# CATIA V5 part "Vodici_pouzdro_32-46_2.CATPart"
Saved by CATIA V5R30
Part number: Vodici_pouzdro_32-46_2
Definition: E 1100_32-46
Nomenclature: E 1100_32-46
Source: Unknown
Description: PART--DESC
Bounding box of the stored display mesh (mm): x 163.7 to 210.3, y 113.7 to 160.3, z -101 to -46
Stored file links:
  E:\Bakalarka\Model\Forma_v7\Vodici_pouzdro_32-46_2.CATPart
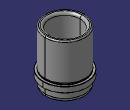
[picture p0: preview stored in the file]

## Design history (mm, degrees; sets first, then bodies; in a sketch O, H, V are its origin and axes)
Body1 "MANIFOLD_SOLID_BREP #3930" (main body)
  Solid1: solid without history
